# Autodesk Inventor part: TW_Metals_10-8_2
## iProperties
Shininess: 64.0
Length Units: 11272
Angle Units: 11279
Time Units: 11290
Mass Units: 11286
Length Display Precision: 3
Angle Display Precision: 2
Compacted: True
Part Number: TW_Metals_10-8_2
Document SubType Name: Modeling
Created: 2005-05
Designer: John Blackburn
Material: Aluminum-6061
Manufacturer: Standard
Standards Organization: Custom
Density: 0.0
Volumn: 0.0
Area: 0.0
PropertySet Name: Model Information
Control State: 0
Master: False
Checked Out: False
Author: John Blackburn
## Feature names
1. Extrusion1
